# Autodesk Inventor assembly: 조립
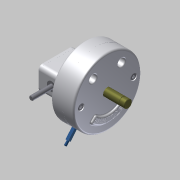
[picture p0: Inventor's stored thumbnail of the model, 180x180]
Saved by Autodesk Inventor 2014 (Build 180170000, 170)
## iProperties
Created: 2015-05
Part Number: 조립
Document SubType Name: Assembly
Designer: Administrator
Mass: 3964.99 g
Surface Area: 3333.71 cm^2
Volume: 1140.85 cm^3
Density: 3.47547 g/cm^3
Author: Administrator
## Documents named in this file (15)
- C:\Documents and Settings\Administrator\바탕 화면\350406V1018\조립.iam
- C:\Documents and Settings\Administrator\바탕 화면\350406V1018\본체.ipt
- C:\Documents and Settings\Administrator\바탕 화면\350406V1018\커버.ipt
- C:\Documents and Settings\Administrator\바탕 화면\350406V1018\M 10 x 35.ipt
- C:\Documents and Settings\Administrator\바탕 화면\350406V1018\축.ipt
- C:\Documents and Settings\Administrator\바탕 화면\350406V1018\멈춤링.ipt
- C:\Documents and Settings\Administrator\바탕 화면\350406V1018\베어링62_22.ipt
- C:\Documents and Settings\Administrator\바탕 화면\350406V1018\커버2.ipt
- C:\Documents and Settings\Administrator\바탕 화면\350406V1018\M 5 x 12.ipt
- C:\Documents and Settings\Administrator\바탕 화면\350406V1018\부시.ipt
- C:\Documents and Settings\Administrator\바탕 화면\350406V1018\스프링-[가변].ipt
- C:\Documents and Settings\Administrator\바탕 화면\350406V1018\슬라이더2.ipt
- C:\Documents and Settings\Administrator\바탕 화면\350406V1018\슬라이더.ipt
- C:\Documents and Settings\Administrator\바탕 화면\350406V1018\평행핀.ipt
- C:\Documents and Settings\Administrator\바탕 화면\350406V1018\슬라이더3.ipt
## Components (5 placed, 3 different names)
1. M 10 x 35:1
2. M 10 x 35:2
3. M 5 x 12:1
4. M 5 x 12:2
5. KS B 1320 B B 5 x  20:1 — 플러쉬:1
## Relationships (1: Flush 1)
- 플러쉬:1 [Flush]: KS B 1320 B B 5 x  20:1
